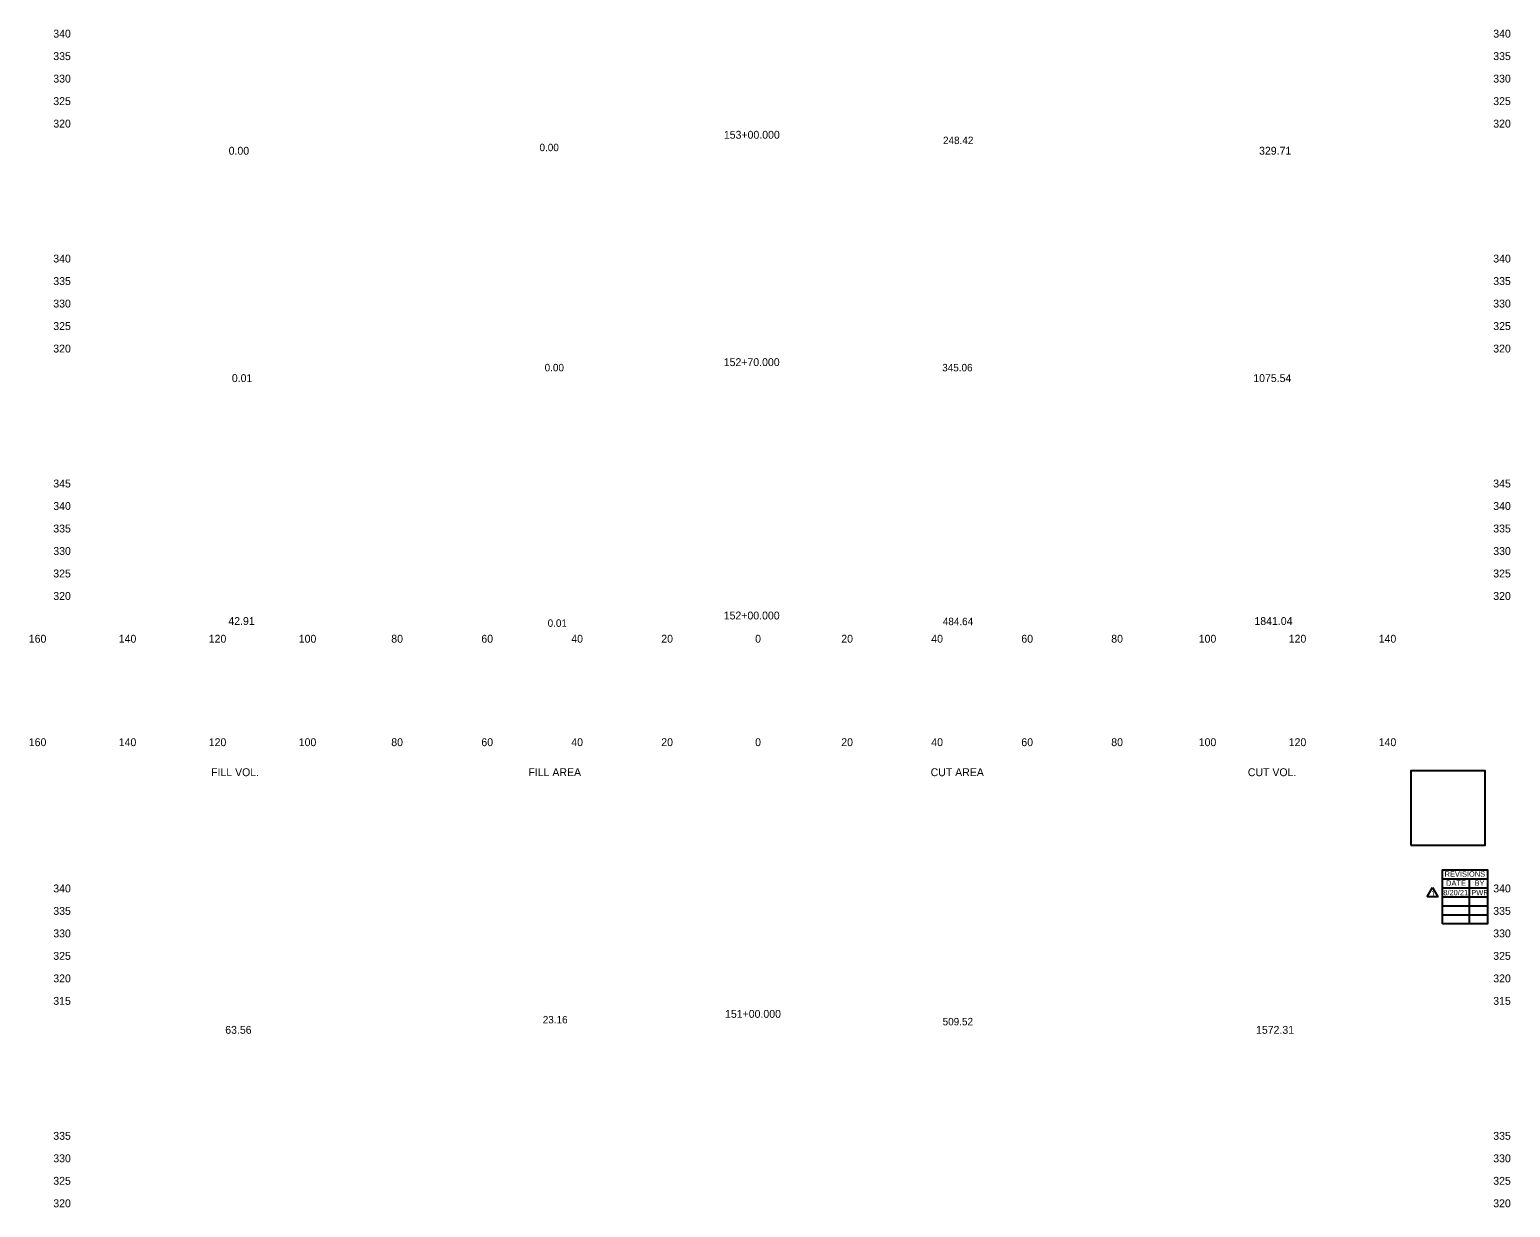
# Model space of a CAD drawing. Extents: x 21477 to 21806, y 6470 to 11049.
# Drawn here: x 21477.1 to 21806.1, y 10484.8 to 10746.6 of the extents above; entities that cross this region are included whole.
import ezdxf

# ---------------------------------------------------------------- set-up
doc = ezdxf.new("R2010")
doc.units = 0
for name, color, linetype in [('ROW_REVISION_DATA', 7, 'Continuous'), ('SHEET_CONSULTANT_STAMP', 7, 'Continuous'), ('XS_SHEET_EW_TX_AREA', 7, 'Continuous'), ('XS_SHEET_EW_TX_VOLUME', 7, 'Continuous'), ('XS_SHEET_LABELS_ELEVATION', 7, 'Continuous'), ('XS_SHEET_LABELS_OFFSET', 7, 'Continuous'), ('XS_SHEET_LABELS_STATION', 7, 'Continuous'), ('XS_SHEET_TX', 7, 'Continuous')]:
    doc.layers.add(name, color=color, linetype=linetype)

msp = doc.modelspace()

# ---------------------------------------------------------------- linework, layer by layer
at = {"layer": 'ROW_REVISION_DATA'}
for p, q in [((21791.04, 10557.84), (21801.04, 10557.84)), ((21797.04, 10547.84), (21797.04, 10557.84)), ((21801.04, 10559.84), (21801.04, 10547.84)), ((21787.64, 10553.84), (21788.84, 10555.92)), ((21791.04, 10555.84), (21801.04, 10555.84)), ((21791.04, 10553.84), (21801.04, 10553.84)), ((21791.04, 10551.84), (21801.04, 10551.84)), ((21797.04, 10551.84), (21797.04, 10551.84)), ((21791.04, 10549.84), (21801.04, 10549.84))]:
    msp.add_line(p, q, dxfattribs=at)
msp.add_lwpolyline([(21791.04, 10547.84), (21791.04, 10559.84), (21801.04, 10559.84), (21801.04, 10547.84)], close=True, dxfattribs=at)
msp.add_lwpolyline([(21788.84, 10555.92), (21790.04, 10553.84), (21787.64, 10553.84)], dxfattribs=at)
at = {"layer": 'SHEET_CONSULTANT_STAMP'}
msp.add_lwpolyline([(21784.04, 10565.34), (21800.54, 10565.34), (21800.54, 10581.84), (21784.04, 10581.84)], close=True, dxfattribs=at)

# ---------------------------------------------------------------- texts
at = {"layer": 'ROW_REVISION_DATA'}
for s, height, p in [('REVISIONS', 1.2, (21791.52, 10558.31)), ('DATE', 1.2, (21791.86, 10556.29)), ('BY', 1.2, (21798.19, 10556.3)), ('1', 1.32, (21788.57, 10553.98)), ('8/20/21 ', 1.2, (21791.24, 10554.18)), ('PWR', 1.2, (21797.46, 10554.18))]:
    msp.add_text(s, height=height, dxfattribs=at).set_placement(p)
at = {"layer": 'XS_SHEET_EW_TX_AREA'}
for s, p in [(' 0.00 ', (21589.78, 10719.59)), (' 248.42 ', (21679.45, 10721.17)), (' 0.00 ', (21590.92, 10670.66)), (' 345.06 ', (21679.27, 10670.66)), (' 484.64 ', (21679.4, 10614.23)), (' 0.01 ', (21591.59, 10613.86)), (' 23.16 ', (21590.5, 10525.72)), (' 509.52 ', (21679.37, 10525.28))]:
    msp.add_text(s, height=1.65, dxfattribs=at).set_placement(p)
at = {"layer": 'XS_SHEET_EW_TX_VOLUME'}
for s, p in [(' 0.00 ', (21520.66, 10718.81)), (' 329.71 ', (21749.65, 10718.81)), (' 0.01 ', (21521.37, 10668.27)), (' 1075.54 ', (21748.36, 10668.27)), (' 42.91 ', (21520.59, 10614.27)), (' 1841.04 ', (21748.62, 10614.27)), (' 63.56 ', (21519.9, 10523.4)), (' 1572.31 ', (21748.97, 10523.4))]:
    msp.add_text(s, height=1.75, dxfattribs=at).set_placement(p)
at = {"layer": 'XS_SHEET_LABELS_ELEVATION'}
for s, p in [('  340  ', (21481.04, 10744.84)), ('  340  ', (21801.04, 10744.84)), ('  335  ', (21481.04, 10739.84)), ('  335  ', (21801.04, 10739.84)), ('  330  ', (21481.04, 10734.84)), ('  330  ', (21801.04, 10734.84)), ('  325  ', (21481.04, 10729.84)), ('  325  ', (21801.04, 10729.84)), ('  320  ', (21481.04, 10724.84)), ('  320  ', (21801.04, 10724.84)), ('  340  ', (21481.04, 10694.84)), ('  340  ', (21801.04, 10694.84)), ('  335  ', (21481.04, 10689.84)), ('  335  ', (21801.04, 10689.84)), ('  330  ', (21481.04, 10684.84)), ('  330  ', (21801.04, 10684.84)), ('  325  ', (21481.04, 10679.84)), ('  325  ', (21801.04, 10679.84)), ('  320  ', (21481.04, 10674.84)), ('  320  ', (21801.04, 10674.84)), ('  345  ', (21481.04, 10644.84)), ('  345  ', (21801.04, 10644.84)), ('  340  ', (21481.04, 10639.84)), ('  340  ', (21801.04, 10639.84)), ('  335  ', (21481.04, 10634.84)), ('  335  ', (21801.04, 10634.84)), ('  330  ', (21481.04, 10629.84)), ('  330  ', (21801.04, 10629.84)), ('  325  ', (21481.04, 10624.84)), ('  325  ', (21801.04, 10624.84)), ('  320  ', (21481.04, 10619.84)), ('  320  ', (21801.04, 10619.84)), ('  340  ', (21481.04, 10554.84)), ('  340  ', (21801.04, 10554.84)), ('  335  ', (21481.04, 10549.84)), ('  335  ', (21801.04, 10549.84)), ('  330  ', (21481.04, 10544.84)), ('  330  ', (21801.04, 10544.84)), ('  325  ', (21481.04, 10539.84)), ('  325  ', (21801.04, 10539.84)), ('  320  ', (21481.04, 10534.84)), ('  320  ', (21801.04, 10534.84)), ('  315  ', (21481.04, 10529.84)), ('  315  ', (21801.04, 10529.84)), ('  335  ', (21481.04, 10499.84)), ('  335  ', (21801.04, 10499.84)), ('  330  ', (21481.04, 10494.84)), ('  330  ', (21801.04, 10494.84)), ('  325  ', (21481.04, 10489.84)), ('  325  ', (21801.04, 10489.84)), ('  320  ', (21481.04, 10484.84)), ('  320  ', (21801.04, 10484.84))]:
    msp.add_text(s, height=1.75, dxfattribs=at).set_placement(p)
at = {"layer": 'XS_SHEET_LABELS_OFFSET'}
for s, p in [('  160  ', (21475.6, 10610.34)), ('  140  ', (21495.59, 10610.34)), ('  120  ', (21515.59, 10610.34)), ('  100  ', (21535.59, 10610.34)), ('  80  ', (21556.15, 10610.34)), ('  60  ', (21576.17, 10610.34)), ('  40  ', (21596.15, 10610.34)), ('  20  ', (21616.15, 10610.34)), ('  0  ', (21637.01, 10610.34)), ('  0  ', (21637.01, 10610.34)), ('  20  ', (21656.15, 10610.34)), ('  40  ', (21676.15, 10610.34)), ('  60  ', (21696.17, 10610.34)), ('  80  ', (21716.15, 10610.34)), ('  100  ', (21735.59, 10610.34)), ('  120  ', (21755.59, 10610.34)), ('  140  ', (21775.59, 10610.34)), ('  160  ', (21475.6, 10587.34)), ('  140  ', (21495.59, 10587.34)), ('  120  ', (21515.59, 10587.34)), ('  100  ', (21535.59, 10587.34)), ('  80  ', (21556.15, 10587.34)), ('  60  ', (21576.17, 10587.34)), ('  40  ', (21596.15, 10587.34)), ('  20  ', (21616.15, 10587.34)), ('  0  ', (21637.01, 10587.34)), ('  0  ', (21637.01, 10587.34)), ('  20  ', (21656.15, 10587.34)), ('  40  ', (21676.15, 10587.34)), ('  60  ', (21696.17, 10587.34)), ('  80  ', (21716.15, 10587.34)), ('  100  ', (21735.59, 10587.34)), ('  120  ', (21755.59, 10587.34)), ('  140  ', (21775.59, 10587.34))]:
    msp.add_text(s, height=1.75, dxfattribs=at).set_placement(p)
at = {"layer": 'XS_SHEET_LABELS_STATION'}
for s, p in [('  153+00.000  ', (21630.06, 10722.36)), ('  152+70.000  ', (21630.03, 10671.82)), ('  152+00.000  ', (21630.03, 10615.5)), ('  151+00.000  ', (21630.32, 10526.95))]:
    msp.add_text(s, height=1.75, dxfattribs=at).set_placement(p)
at = {"layer": 'XS_SHEET_TX'}
for s, p in [('FILL VOL.', (21517.41, 10580.67)), ('FILL AREA', (21587.92, 10580.67)), ('CUT AREA', (21677.31, 10580.67)), ('CUT VOL.', (21747.8, 10580.67))]:
    msp.add_text(s, height=1.75, dxfattribs=at).set_placement(p)

doc.saveas('drawing.dxf')
